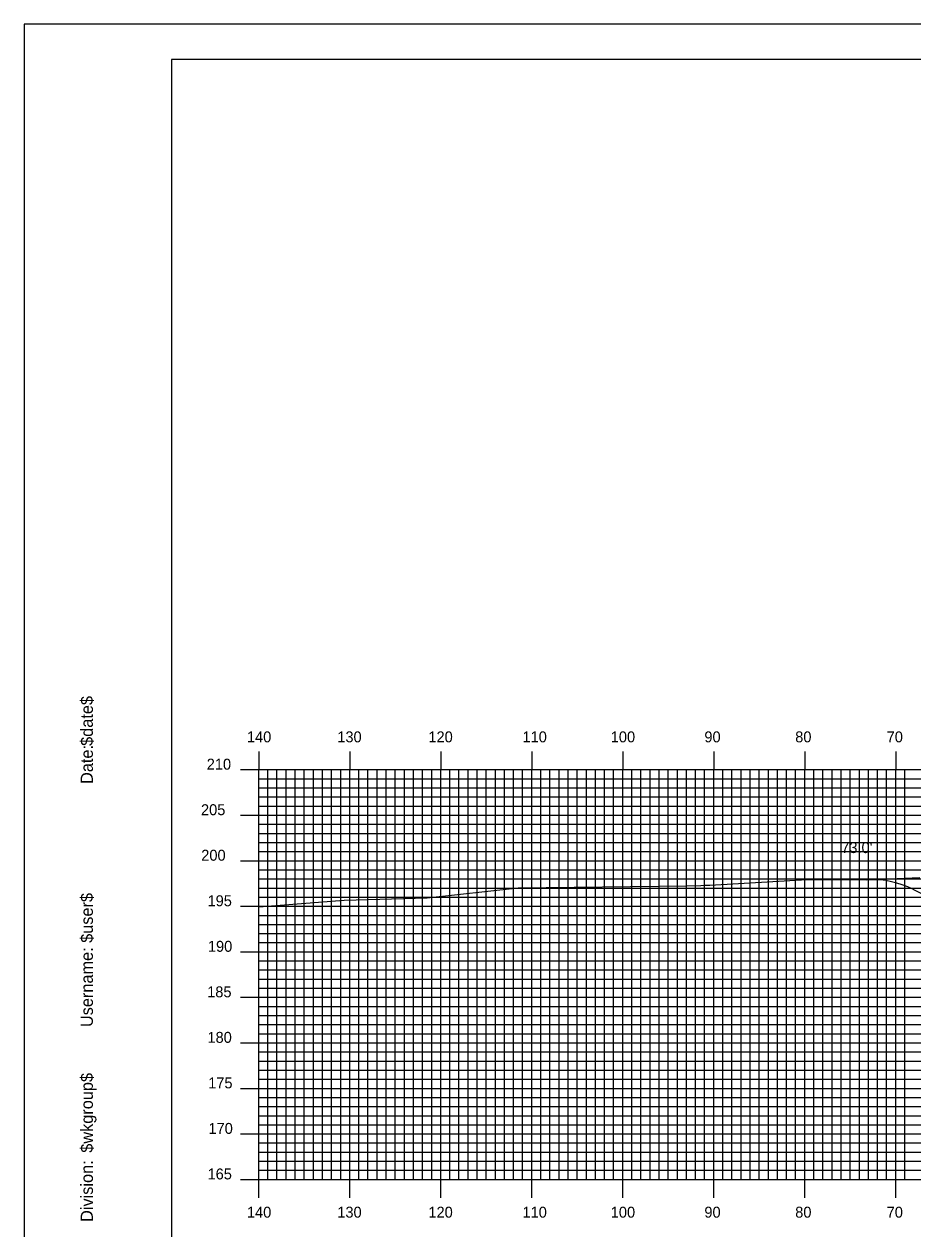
# Model space of a CAD drawing. Extents: x 1795240 to 1795583, y 442591 to 442811.
# Drawn here: x 1795239.6 to 1795337.3, y 442678.2 to 442810.5 of the extents above; entities that cross this region are included whole.
import ezdxf

# ---------------------------------------------------------------- set-up
doc = ezdxf.new("R2010")
doc.units = 0
for name, color, linetype in [('BORDER', 7, 'Continuous'), ('D_Roadway_Centerline', 7, 'Continuous'), ('D_Text_Standard', 7, 'Continuous'), ('H_V ANNOTATION', 7, 'Continuous'), ('MAJOR', 7, 'Continuous'), ('MINOR', 7, 'Continuous'), ('PLOT BOUNDARY', 7, 'Continuous'), ('S_Roadway_Centerline', 7, 'Continuous')]:
    doc.layers.add(name, color=color, linetype=linetype)

msp = doc.modelspace()

# ---------------------------------------------------------------- linework, layer by layer
at = {"layer": 'BORDER'}
msp.add_lwpolyline([(1795255.77, 442596.67), (1795575.77, 442596.67), (1795575.77, 442806.67), (1795255.77, 442806.67)], close=True, dxfattribs=at)
at = {"layer": 'D_Roadway_Centerline'}
msp.add_lwpolyline([(1795337.26, 442715.54), (1795361.8, 442703.27), (1795367.8, 442703.27), (1795371.19, 442689.7), (1795375.19, 442690.7), (1795385.37, 442693.25), (1795393.37, 442693.57), (1795405.37, 442693.33), (1795417.37, 442693.09), (1795425.37, 442692.77), (1795435.54, 442690.22), (1795439.54, 442689.22), (1795444.37, 442708.53)], dxfattribs=at)
msp.add_arc((1795332.78, 442706.59), 10, 63.4349, 92.2588, dxfattribs=at)
at = {"layer": 'MAJOR'}
for p, q in [((1795265.37, 442730.67), (1795265.37, 442728.67)), ((1795275.37, 442730.67), (1795275.37, 442728.67)), ((1795285.37, 442730.67), (1795285.37, 442728.67)), ((1795295.37, 442730.67), (1795295.37, 442728.67)), ((1795305.37, 442730.67), (1795305.37, 442728.67)), ((1795315.37, 442730.67), (1795315.37, 442728.67)), ((1795325.37, 442730.67), (1795325.37, 442728.67)), ((1795335.37, 442730.67), (1795335.37, 442728.67)), ((1795263.36, 442728.67), (1795265.37, 442728.67)), ((1795265.37, 442728.67), (1795545.37, 442728.67)), ((1795265.37, 442683.67), (1795265.37, 442728.67)), ((1795265.37, 442683.67), (1795265.37, 442728.67)), ((1795265.37, 442728.67), (1795545.37, 442728.67)), ((1795275.37, 442683.67), (1795275.37, 442728.67)), ((1795285.37, 442683.67), (1795285.37, 442728.67)), ((1795295.37, 442683.67), (1795295.37, 442728.67)), ((1795305.37, 442683.67), (1795305.37, 442728.67)), ((1795315.37, 442683.67), (1795315.37, 442728.67)), ((1795325.37, 442683.67), (1795325.37, 442728.67)), ((1795335.37, 442683.67), (1795335.37, 442728.67)), ((1795263.36, 442723.67), (1795265.37, 442723.67)), ((1795265.37, 442723.67), (1795545.37, 442723.67)), ((1795263.36, 442718.67), (1795265.37, 442718.67)), ((1795265.37, 442718.67), (1795545.37, 442718.67)), ((1795263.36, 442713.67), (1795265.37, 442713.67)), ((1795265.37, 442713.67), (1795545.37, 442713.67)), ((1795263.36, 442708.67), (1795265.37, 442708.67)), ((1795265.37, 442708.67), (1795545.37, 442708.67)), ((1795263.36, 442703.67), (1795265.37, 442703.67)), ((1795265.37, 442703.67), (1795545.37, 442703.67)), ((1795263.36, 442698.67), (1795265.37, 442698.67)), ((1795265.37, 442698.67), (1795545.37, 442698.67)), ((1795263.36, 442693.67), (1795265.37, 442693.67)), ((1795265.37, 442693.67), (1795545.37, 442693.67)), ((1795263.36, 442688.67), (1795265.37, 442688.67)), ((1795265.37, 442688.67), (1795545.37, 442688.67)), ((1795263.36, 442683.67), (1795265.37, 442683.67)), ((1795265.37, 442683.67), (1795545.37, 442683.67)), ((1795265.37, 442683.67), (1795545.37, 442683.67)), ((1795265.37, 442681.66), (1795265.37, 442683.67)), ((1795275.37, 442681.66), (1795275.37, 442683.67)), ((1795285.37, 442681.66), (1795285.37, 442683.67)), ((1795295.37, 442681.66), (1795295.37, 442683.67)), ((1795305.37, 442681.66), (1795305.37, 442683.67)), ((1795315.37, 442681.66), (1795315.37, 442683.67)), ((1795325.37, 442681.66), (1795325.37, 442683.67)), ((1795335.37, 442681.66), (1795335.37, 442683.67))]:
    msp.add_line(p, q, dxfattribs=at)
at = {"layer": 'MINOR'}
for p, q in [((1795266.37, 442683.67), (1795266.37, 442728.67)), ((1795267.37, 442683.67), (1795267.37, 442728.67)), ((1795268.37, 442683.67), (1795268.37, 442728.67)), ((1795269.37, 442683.67), (1795269.37, 442728.67)), ((1795270.37, 442683.67), (1795270.37, 442728.67)), ((1795271.37, 442683.67), (1795271.37, 442728.67)), ((1795272.37, 442683.67), (1795272.37, 442728.67)), ((1795273.37, 442683.67), (1795273.37, 442728.67)), ((1795274.37, 442683.67), (1795274.37, 442728.67)), ((1795276.37, 442683.67), (1795276.37, 442728.67)), ((1795277.37, 442683.67), (1795277.37, 442728.67)), ((1795278.37, 442683.67), (1795278.37, 442728.67)), ((1795279.37, 442683.67), (1795279.37, 442728.67)), ((1795280.37, 442683.67), (1795280.37, 442728.67)), ((1795281.37, 442683.67), (1795281.37, 442728.67)), ((1795282.37, 442683.67), (1795282.37, 442728.67)), ((1795283.37, 442683.67), (1795283.37, 442728.67)), ((1795284.37, 442683.67), (1795284.37, 442728.67)), ((1795286.37, 442683.67), (1795286.37, 442728.67)), ((1795287.37, 442683.67), (1795287.37, 442728.67)), ((1795288.37, 442683.67), (1795288.37, 442728.67)), ((1795289.37, 442683.67), (1795289.37, 442728.67)), ((1795290.37, 442683.67), (1795290.37, 442728.67)), ((1795291.37, 442683.67), (1795291.37, 442728.67)), ((1795292.37, 442683.67), (1795292.37, 442728.67)), ((1795293.37, 442683.67), (1795293.37, 442728.67)), ((1795294.37, 442683.67), (1795294.37, 442728.67)), ((1795296.37, 442683.67), (1795296.37, 442728.67)), ((1795297.37, 442683.67), (1795297.37, 442728.67)), ((1795298.37, 442683.67), (1795298.37, 442728.67)), ((1795299.37, 442683.67), (1795299.37, 442728.67)), ((1795300.37, 442683.67), (1795300.37, 442728.67)), ((1795301.37, 442683.67), (1795301.37, 442728.67)), ((1795302.37, 442683.67), (1795302.37, 442728.67)), ((1795303.37, 442683.67), (1795303.37, 442728.67)), ((1795304.37, 442683.67), (1795304.37, 442728.67)), ((1795306.37, 442683.67), (1795306.37, 442728.67)), ((1795307.37, 442683.67), (1795307.37, 442728.67)), ((1795308.37, 442683.67), (1795308.37, 442728.67)), ((1795309.37, 442683.67), (1795309.37, 442728.67)), ((1795310.37, 442683.67), (1795310.37, 442728.67)), ((1795311.37, 442683.67), (1795311.37, 442728.67)), ((1795312.37, 442683.67), (1795312.37, 442728.67)), ((1795313.37, 442683.67), (1795313.37, 442728.67)), ((1795314.37, 442683.67), (1795314.37, 442728.67)), ((1795316.37, 442683.67), (1795316.37, 442728.67)), ((1795317.37, 442683.67), (1795317.37, 442728.67)), ((1795318.37, 442683.67), (1795318.37, 442728.67)), ((1795319.37, 442683.67), (1795319.37, 442728.67)), ((1795320.37, 442683.67), (1795320.37, 442728.67)), ((1795321.37, 442683.67), (1795321.37, 442728.67)), ((1795322.37, 442683.67), (1795322.37, 442728.67)), ((1795323.37, 442683.67), (1795323.37, 442728.67)), ((1795324.37, 442683.67), (1795324.37, 442728.67)), ((1795326.37, 442683.67), (1795326.37, 442728.67)), ((1795327.37, 442683.67), (1795327.37, 442728.67)), ((1795328.37, 442683.67), (1795328.37, 442728.67)), ((1795329.37, 442683.67), (1795329.37, 442728.67)), ((1795330.37, 442683.67), (1795330.37, 442728.67)), ((1795331.37, 442683.67), (1795331.37, 442728.67)), ((1795332.37, 442683.67), (1795332.37, 442728.67)), ((1795333.37, 442683.67), (1795333.37, 442728.67)), ((1795334.37, 442683.67), (1795334.37, 442728.67)), ((1795336.37, 442683.67), (1795336.37, 442728.67)), ((1795265.37, 442727.67), (1795545.37, 442727.67)), ((1795265.37, 442727.67), (1795267.37, 442727.67)), ((1795265.37, 442726.67), (1795545.37, 442726.67)), ((1795265.37, 442726.67), (1795267.37, 442726.67)), ((1795265.37, 442725.67), (1795545.37, 442725.67)), ((1795265.37, 442725.67), (1795267.37, 442725.67)), ((1795265.37, 442724.67), (1795545.37, 442724.67)), ((1795265.37, 442724.67), (1795267.37, 442724.67)), ((1795265.37, 442722.67), (1795545.37, 442722.67)), ((1795265.37, 442722.67), (1795267.37, 442722.67)), ((1795265.37, 442721.67), (1795545.37, 442721.67)), ((1795265.37, 442721.67), (1795267.37, 442721.67)), ((1795265.37, 442720.67), (1795545.37, 442720.67)), ((1795265.37, 442720.67), (1795267.37, 442720.67)), ((1795265.37, 442719.67), (1795545.37, 442719.67)), ((1795265.37, 442719.67), (1795267.37, 442719.67)), ((1795265.37, 442717.67), (1795545.37, 442717.67)), ((1795265.37, 442717.67), (1795267.37, 442717.67)), ((1795265.37, 442716.67), (1795545.37, 442716.67)), ((1795265.37, 442716.67), (1795267.37, 442716.67)), ((1795265.37, 442715.67), (1795545.37, 442715.67)), ((1795265.37, 442715.67), (1795267.37, 442715.67)), ((1795265.37, 442714.67), (1795545.37, 442714.67)), ((1795265.37, 442714.67), (1795267.37, 442714.67)), ((1795265.37, 442712.67), (1795545.37, 442712.67)), ((1795265.37, 442712.67), (1795267.37, 442712.67)), ((1795265.37, 442711.67), (1795545.37, 442711.67)), ((1795265.37, 442711.67), (1795267.37, 442711.67)), ((1795265.37, 442710.67), (1795545.37, 442710.67)), ((1795265.37, 442710.67), (1795267.37, 442710.67)), ((1795265.37, 442709.67), (1795545.37, 442709.67)), ((1795265.37, 442709.67), (1795267.37, 442709.67)), ((1795265.37, 442707.67), (1795545.37, 442707.67)), ((1795265.37, 442707.67), (1795267.37, 442707.67)), ((1795265.37, 442706.67), (1795545.37, 442706.67)), ((1795265.37, 442706.67), (1795267.37, 442706.67)), ((1795265.37, 442705.67), (1795545.37, 442705.67)), ((1795265.37, 442705.67), (1795267.37, 442705.67)), ((1795265.37, 442704.67), (1795545.37, 442704.67)), ((1795265.37, 442704.67), (1795267.37, 442704.67)), ((1795265.37, 442702.67), (1795545.37, 442702.67)), ((1795265.37, 442702.67), (1795267.37, 442702.67)), ((1795265.37, 442701.67), (1795545.37, 442701.67)), ((1795265.37, 442701.67), (1795267.37, 442701.67)), ((1795265.37, 442700.67), (1795545.37, 442700.67)), ((1795265.37, 442700.67), (1795267.37, 442700.67)), ((1795265.37, 442699.67), (1795545.37, 442699.67)), ((1795265.37, 442699.67), (1795267.37, 442699.67)), ((1795265.37, 442697.67), (1795545.37, 442697.67)), ((1795265.37, 442697.67), (1795267.37, 442697.67)), ((1795265.37, 442696.67), (1795545.37, 442696.67)), ((1795265.37, 442696.67), (1795267.37, 442696.67)), ((1795265.37, 442695.67), (1795545.37, 442695.67)), ((1795265.37, 442695.67), (1795267.37, 442695.67)), ((1795265.37, 442694.67), (1795545.37, 442694.67)), ((1795265.37, 442694.67), (1795267.37, 442694.67)), ((1795265.37, 442692.67), (1795545.37, 442692.67)), ((1795265.37, 442692.67), (1795267.37, 442692.67)), ((1795265.37, 442691.67), (1795545.37, 442691.67)), ((1795265.37, 442691.67), (1795267.37, 442691.67)), ((1795265.37, 442690.67), (1795545.37, 442690.67)), ((1795265.37, 442690.67), (1795267.37, 442690.67)), ((1795265.37, 442689.67), (1795545.37, 442689.67)), ((1795265.37, 442689.67), (1795267.37, 442689.67)), ((1795265.37, 442687.67), (1795545.37, 442687.67)), ((1795265.37, 442687.67), (1795267.37, 442687.67)), ((1795265.37, 442686.67), (1795545.37, 442686.67)), ((1795265.37, 442686.67), (1795267.37, 442686.67)), ((1795265.37, 442685.67), (1795545.37, 442685.67)), ((1795265.37, 442685.67), (1795267.37, 442685.67)), ((1795265.37, 442684.67), (1795545.37, 442684.67)), ((1795265.37, 442684.67), (1795267.37, 442684.67))]:
    msp.add_line(p, q, dxfattribs=at)
at = {"layer": 'PLOT BOUNDARY'}
msp.add_lwpolyline([(1795239.58, 442590.55), (1795579.58, 442590.55), (1795579.58, 442810.55), (1795239.58, 442810.55)], close=True, dxfattribs=at)
at = {"layer": 'S_Roadway_Centerline'}
msp.add_lwpolyline([(1795265.37, 442713.6), (1795274.76, 442714.32), (1795283.88, 442714.59), (1795293.86, 442715.68), (1795312.36, 442715.92), (1795313.96, 442715.95), (1795314.34, 442715.97), (1795314.93, 442716), (1795325.63, 442716.59), (1795332.2, 442716.58), (1795338.01, 442716.81)], dxfattribs=at)

# ---------------------------------------------------------------- texts
at = {"layer": 'BORDER'}
for s, p in [('$date$', (1795247.14, 442731.28)), ('Date:', (1795247.14, 442727.1)), ('$user$', (1795247.14, 442709.65)), ('Username:', (1795247.14, 442700.4)), ('$wkgroup$', (1795247.14, 442686.6)), ('Division:', (1795247.14, 442679))]:
    msp.add_text(s, height=1.339, rotation=90, dxfattribs=at).set_placement(p)
at = {"layer": 'D_Text_Standard'}
msp.add_text("73.0'", height=1.2, dxfattribs=at).set_placement((1795329.38, 442719.51))
at = {"layer": 'H_V ANNOTATION'}
for s, p in [('140', (1795264.07, 442731.67)), ('130', (1795274, 442731.67)), ('120', (1795284.01, 442731.67)), ('110', (1795294.35, 442731.67)), ('100', (1795304.05, 442731.67)), ('90', (1795314.34, 442731.67)), ('80', (1795324.32, 442731.67)), ('70', (1795334.37, 442731.67)), ('210', (1795259.65, 442728.67)), ('205', (1795259.02, 442723.67)), ('200', (1795259.05, 442718.67)), ('195', (1795259.74, 442713.67)), ('190', (1795259.78, 442708.67)), ('185', (1795259.7, 442703.67)), ('180', (1795259.73, 442698.67)), ('175', (1795259.81, 442693.67)), ('170', (1795259.84, 442688.67)), ('165', (1795259.74, 442683.67)), ('140', (1795264.07, 442679.47)), ('130', (1795274, 442679.47)), ('120', (1795284.01, 442679.47)), ('110', (1795294.35, 442679.47)), ('100', (1795304.05, 442679.47)), ('90', (1795314.34, 442679.47)), ('80', (1795324.32, 442679.47)), ('70', (1795334.37, 442679.47))]:
    msp.add_text(s, height=1.2, dxfattribs=at).set_placement(p)
at = {"layer": 'MAJOR'}
msp.add_text('-', height=0.012, dxfattribs=at).set_placement((1795265.36, 442683.67))

doc.saveas('drawing.dxf')
